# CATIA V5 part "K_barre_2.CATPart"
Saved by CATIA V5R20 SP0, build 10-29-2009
Part number: barre_2
Bounding box of the stored display mesh (mm): x -16.009 to 2.493, y -12 to -11, z 41.001 to 52.493
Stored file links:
  G:\Khaled_CFAO_2011\ST2M\ST2M_GR2\gcausse\Khaled\CAD_ThinkMotion\K_barre_2.CATPart
  C:\Documents and Settings\gcausse\Bureau\video thinkmotio\assemblage_gcausse\pupitre_think.CATProduct
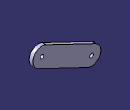
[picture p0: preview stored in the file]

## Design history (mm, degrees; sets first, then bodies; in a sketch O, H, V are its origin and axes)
Set1
  Sketch1 on Plane1, origin (0, -12, 0), H (-1, 0, 0), V (0, 0, 1)
    line L1 (1.0843, 52.2526) -> (14.6, 45.7467)
    arc A1 centre (13.5157, 43.4941) radius 2.5 from (14.6, 45.7467) to (12.4313, 41.2415) cw
    point P3 (13.5157, 43.4941)
    line L2 (12.4313, 41.2415) -> (-1.0843, 47.7474)
    arc A2 centre (0, 50) radius 2.5 from (-1.0843, 47.7474) to (1.0843, 52.2526) cw
    point P6 (0, 50)
    reference projected point E1 (0, 50) from Point1
    reference projected point E2 (13.5157, 43.4941) from Point2
    reference projected line E3 (0, 50) -> (13.5157, 43.4941) from Line1
    distance L1 L2 = 5
    tangency: A1 L1, L2 A1, A2 L1, A2 L2
    coincidence: E1 P6, P3 E2
    parallelism: L1 E3
Set2
  Plane1: linked copy from another document
  Point1: linked copy from another document
  Point2: linked copy from another document
  Line1: linked copy from another document
Body1 (main body)
  Pad1: profile Sketch1, direction (0, 1, 0), length 1
  Sketch2 on start face of Pad1, origin (-5.9638, -12, 48.2348), H (1, 0, 0), V (0, 0, 1)
    point P1 (5.9638, 1.7652)
    reference projected point E1 (5.9638, 1.7652) from Point1
    coincidence: P1 E1
  Hole1: placed by Sketch2, at (0, -12, 50) direction (0, 1, 0), diameter 1, depth 1
  Sketch3 on start face of Pad1, origin (-11.3588, -12, 46.4147), H (1, 0, 0), V (0, 0, 1)
    point P1 (-2.1569, -2.9206)
    reference projected point E1 (-2.1569, -2.9206) from Point2
    coincidence: P1 E1
  Hole2: placed by Sketch3, at (-13.5157, -12, 43.4941) direction (0, 1, 0), diameter 1, depth 1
